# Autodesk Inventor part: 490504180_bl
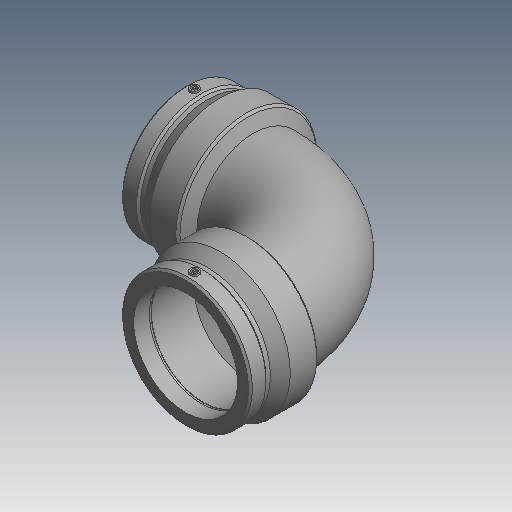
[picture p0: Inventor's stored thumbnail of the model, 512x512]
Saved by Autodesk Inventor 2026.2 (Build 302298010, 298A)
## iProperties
Created: 2017-06
Part Number: 490504180_bl
Material: Generic
Description: PLASSON 90° ELBOW 180
Document SubType Name: Modeling
Designer: KIM
Mass: 55.0731 g
Surface Area: 148.067 cm^2
Volume: 55.0731 cm^3
Density: 1 g/cm^3
Appearance: Default
Author: KIM
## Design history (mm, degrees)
derived "490504.ipt"
feature "Solid1::490504.ipt" dims "ScaleForDerivedMember" = 10
tag "TaggingFeature1"
body "Solid1"
other parameters: "d2" = 244 [user parameter], "d4" = 103 [user parameter], "d5" = 219.6 [user parameter], "d8" = 168 deg [user parameter], "d10" = 42 [user parameter], "d11" = 14 [user parameter], "d14" = 17.6296 [user parameter], "d19" = 3.52592 [user parameter], "d20" = 168 deg [user parameter], "d22" = 224.48 [user parameter], "d23" = 244 [user parameter], "d24" = 217.7456 [user parameter], "d29" = 115 [user parameter], "d30" = 15 [user parameter], "d31" = 144.2 [user parameter], "d34" = 5 deg [user parameter], "d35" = 15 [user parameter], "d39" = 5 deg [user parameter], "d41" = 4 [user parameter], "d42" = 14 [user parameter], "d43" = 0 [user parameter], "d45" = 4 [user parameter], "d46" = 14 [user parameter], "d47" = 0 [user parameter], "d50" = 153 [user parameter], "d51" = 42 [user parameter], "d52" = 105 [user parameter], "d54" = 90 deg [user parameter], "d67" = 45 deg [user parameter], "d71" = 90 deg [user parameter], "d75" = 12.2 [user parameter], "d82" = 45 deg [user parameter], "d83" = 105 [user parameter], "d84" = 219.6 [user parameter], "d87" = 90 deg [user parameter], "d90" = 105 [user parameter], "d91" = 0 [user parameter], "d92" = 105 [user parameter], "d93" = 0 [user parameter], "d94" = 90 deg [user parameter], "d101" = 3 [user parameter], "d102" = 0 [user parameter], "d103" = 3 [user parameter], "d104" = 0 [user parameter], "d105" = 30.45 [user parameter], "d106" = 7.6125 [user parameter], "d110" = 57.75 [user parameter], "d111" = 412 [user parameter], "d112" = 412 [user parameter], "d113" = 412 [user parameter], "d114" = 412 [user parameter], "L_" = 412 [user parameter], "L_1" = 105 [user parameter], "D_" = 244 [user parameter], "A_" = 115 [user parameter], "d_2" = 12 [user parameter]
